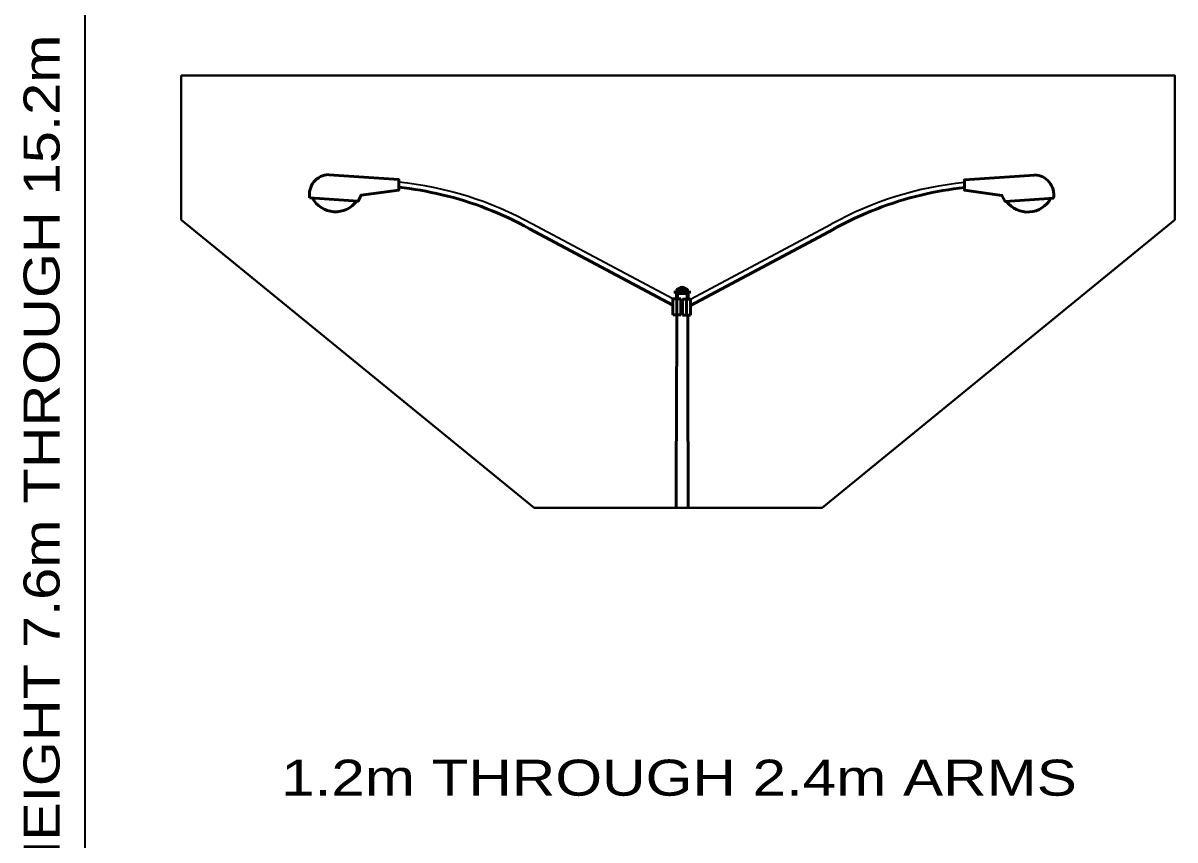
# Model space of a CAD drawing. Extents: x -20 to 693, y -19 to 435.
# Drawn here: x 200.3 to 281.6, y 320.5 to 378.2 of the extents above; entities that cross this region are included whole.
import ezdxf

# ---------------------------------------------------------------- set-up
doc = ezdxf.new("R2010")
doc.units = 0
doc.layers.add('1', color=7, linetype='Continuous', lineweight=53)

msp = doc.modelspace()

# ---------------------------------------------------------------- linework, layer by layer
at = {"layer": '1', "lineweight": 35}
for p, q in [((204.677, 410.341), (204.677, 261.409)), ((246.157, 358.709), (236.228, 363.99)), ((247.417, 358.689), (257.345, 363.97))]:
    msp.add_line(p, q, dxfattribs=at)
at = {"layer": '1', "lineweight": 40}
for p, q in [((211.477, 374.449), (211.477, 364.289)), ((211.477, 364.289), (236.377, 343.969)), ((281.597, 364.289), (256.697, 343.969)), ((236.377, 343.969), (256.697, 343.969))]:
    msp.add_line(p, q, dxfattribs=at)
at = {"layer": '1'}
for p, q in [((246.157, 358.269), (236.047, 363.649)), ((247.417, 358.249), (257.526, 363.63)), ((246.357, 359.269), (247.297, 359.269)), ((246.157, 358.709), (246.737, 358.709)), ((246.157, 358.709), (246.157, 357.569)), ((246.357, 359.089), (247.297, 359.089)), ((246.437, 358.709), (246.437, 357.569)), ((246.737, 358.709), (246.737, 357.569)), ((247.417, 358.689), (246.857, 358.689)), ((246.857, 358.689), (246.857, 357.549)), ((247.137, 358.689), (247.137, 357.549)), ((247.417, 358.689), (247.417, 357.549)), ((246.157, 357.569), (246.737, 357.569)), ((246.437, 357.569), (246.437, 354.509)), ((247.417, 357.549), (246.857, 357.549)), ((247.217, 357.549), (247.217, 354.489)), ((246.437, 354.509), (246.417, 353.369)), ((247.217, 354.489), (247.217, 353.349)), ((246.417, 353.369), (246.397, 343.969)), ((247.217, 353.349), (247.257, 343.969))]:
    msp.add_line(p, q, dxfattribs=at)
at = {"layer": '1', "lineweight": 70}
for p, q in [((246.357, 359.269), (246.357, 359.089)), ((247.297, 359.269), (247.297, 359.089)), ((246.457, 359.089), (246.437, 358.709)), ((247.197, 359.089), (247.197, 358.689))]:
    msp.add_line(p, q, dxfattribs=at)
at = {"layer": '1', "lineweight": 40}
msp.add_lwpolyline([(211.477, 374.449), (281.597, 374.449), (281.597, 364.289)], dxfattribs=at)
at = {"layer": '1', "lineweight": 35}
for points in [[(221.884, 367.459), (226.824, 367.119), (226.824, 366.379), (224.184, 366.019), (223.964, 365.599), (220.544, 365.839), (220.539, 365.834)], [(266.745, 366.376), (266.745, 367.096), (271.685, 367.436)], [(273.045, 365.816), (269.625, 365.576), (269.385, 365.996), (266.745, 366.376)]]:
    msp.add_lwpolyline(points, dxfattribs=at)
at = {"layer": '1'}
for points in [[(221.884, 367.459), (226.824, 367.119), (226.824, 366.379), (224.184, 366.019), (223.964, 365.599), (220.544, 365.839)], [(271.685, 367.436), (266.745, 367.096), (266.745, 366.376), (269.385, 365.996), (269.625, 365.576), (273.045, 365.816)]]:
    msp.add_lwpolyline(points, dxfattribs=at)
for centre, radius, start, end in [((221.929, 366.061), 1.408, 91.83971, 189.27341), ((271.644, 366.041), 1.408, 350.72659, 88.16029), ((224.183, 342.225), 24.495, 76.56687, 83.80757), ((222.367, 366.714), 1.866, 208.61261, 323.3862), ((224.183, 342.225), 24.495, 61.02434, 76.56687), ((269.39, 342.205), 24.495, 103.43307, 118.97566), ((269.39, 342.205), 24.495, 96.19243, 103.43312), ((271.206, 366.694), 1.866, 216.6138, 331.38739)]:
    msp.add_arc(centre, radius, start, end, dxfattribs=at)
at = {"layer": '1', "lineweight": 35}
for centre, radius, start, end in [((221.929, 366.061), 1.408, 91.83971, 189.27341), ((271.644, 366.041), 1.408, 350.72659, 88.16029), ((224.362, 342.562), 24.495, 61.02434, 84.2283), ((269.212, 342.542), 24.495, 95.7717, 118.97566)]:
    msp.add_arc(centre, radius, start, end, dxfattribs=at)
at = {"layer": '1', "lineweight": 70}
msp.add_arc((246.826, 359.011), 0.464, 34.90646, 145.09354, dxfattribs=at)

# ---------------------------------------------------------------- texts
at = {"layer": '1', "width": 1.2}
msp.add_text('MOUNTING HEIGHT 7.6m THROUGH 15.2m', height=2.54, rotation=90, dxfattribs=at).set_placement((202.894, 294.227))
at = {"layer": '1', "width": 1.25}
msp.add_text('1.2m THROUGH 2.4m ARMS', height=2.54, dxfattribs=at).set_placement((218.53, 323.669))

doc.saveas('drawing.dxf')
